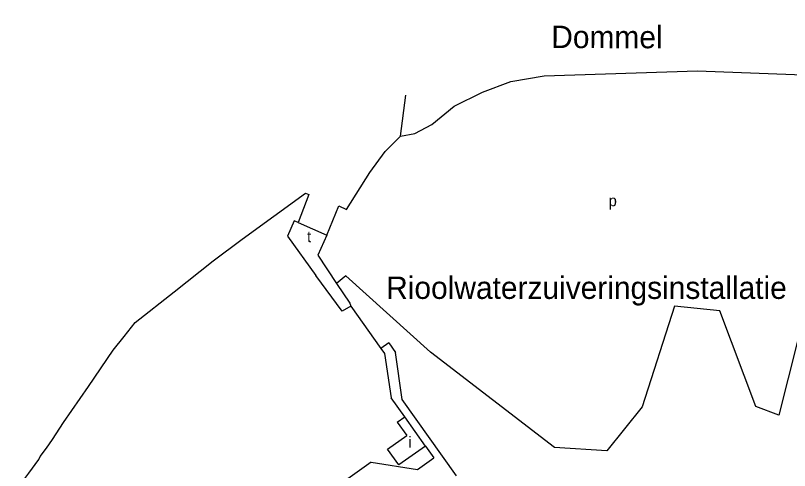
# Model space of a CAD drawing. Extents: x 162427 to 165104, y 384242 to 386287.
# Drawn here: x 162986.7 to 163263.6, y 385814.9 to 385977.6 of the extents above; entities that cross this region are included whole.
import ezdxf

# ---------------------------------------------------------------- set-up
doc = ezdxf.new("R2010")
doc.units = 0
for name, color, linetype in [('BLT_Basislijn', 7, 'Continuous'), ('BLT_Bebouwing', 7, 'Continuous'), ('BLT_Centroide', 7, 'Continuous'), ('BLT_Terrein_beschrifting', 7, 'Continuous'), ('BLT_Vlakafsluiter', 7, 'Continuous'), ('BLT_Waternaam_spoorwegen', 7, 'Continuous')]:
    doc.layers.add(name, color=color, linetype=linetype)

msp = doc.modelspace()

# ---------------------------------------------------------------- linework, layer by layer
at = {"layer": 'BLT_Basislijn'}
for p, q in [((163087.86, 385903.56), (163098.12, 385899.02)), ((163084.03, 385898.67), (163094.14, 385884.68)), ((163098.12, 385899.02), (163094.88, 385891.85)), ((163094.88, 385891.85), (163101.56, 385881.81)), ((163104.9, 385884.54), (163101.56, 385881.81)), ((163135.21, 385857.18), (163104.9, 385884.54)), ((163106.74, 385873.61), (163117.4, 385858.58)), ((163120.24, 385860.59), (163117.4, 385858.58)), ((163120.24, 385860.59), (163122.69, 385857.14)), ((163117.4, 385858.58), (163118.68, 385856.78)), ((163118.68, 385856.78), (163121.09, 385840.94)), ((163125.05, 385840.31), (163122.69, 385857.14)), ((163125.94, 385834.11), (163121.09, 385840.94)), ((163144.44, 385812.98), (163125.05, 385840.31)), ((163133.36, 385823.65), (163136.38, 385819.4)), ((163113.98, 385817.86), (163042.08, 385767.08)), ((163113.98, 385817.86), (163130.49, 385815.22)), ((163130.49, 385815.22), (163136.38, 385819.4))]:
    msp.add_line(p, q, dxfattribs=at)
for points in [[(163124.41, 385934.5), (163129.57, 385935.37), (163135.63, 385938.66), (163143.7, 385945.16), (163153.77, 385950.25), (163163.88, 385954.07), (163175.88, 385956.06), (163230.64, 385957.87), (163290.67, 385955.61), (163310.91, 385957.64), (163330.9, 385965.31), (163350, 385977.63)], [(163098.12, 385899.02), (163102.38, 385909.54), (163105.18, 385908.26), (163113.48, 385921.43), (163118.91, 385928.97), (163124.41, 385934.5)], [(163079.13, 385905.9), (163090.5, 385914.12), (163091.64, 385913.63), (163087.86, 385903.56)], [(163029.49, 385867.77), (163043.44, 385878.84), (163057.39, 385889.9), (163067.77, 385897.68), (163079.13, 385905.9)], [(163087.86, 385903.56), (163086.46, 385904.19), (163084.03, 385898.67)], [(163276.69, 385901.75), (163259.84, 385834.66), (163251.59, 385837.75), (163238.64, 385871.94), (163222.45, 385873.61), (163210.9, 385837.64), (163198.27, 385821.91), (163179.51, 385823.06), (163135.21, 385857.18)], [(163106.74, 385873.61), (163103.55, 385871.86), (163094.14, 385884.68)], [(163101.56, 385881.81), (163106.3, 385874.68), (163106.74, 385873.61)], [(163003.85, 385832.01), (163012.79, 385844.98), (163021.72, 385857.94), (163025.6, 385862.86), (163029.49, 385867.77)], [(162986.73, 385806.97), (162987.92, 385809.21), (162991.49, 385813.99), (162995.07, 385818.77), (162995.6, 385819.85), (162997.8, 385822.92), (163000, 385826), (163003.85, 385832.01)]]:
    msp.add_lwpolyline(points, dxfattribs=at)
at = {"layer": 'BLT_Bebouwing'}
for p, q in [((163123.28, 385832.22), (163125.94, 385834.11)), ((163133.36, 385823.65), (163125.94, 385834.11)), ((163123.28, 385832.22), (163126.71, 385827.38)), ((163119.84, 385822.5), (163126.71, 385827.38)), ((163133.36, 385823.65), (163123.83, 385816.89)), ((163123.83, 385816.89), (163119.84, 385822.5))]:
    msp.add_line(p, q, dxfattribs=at)
at = {"layer": 'BLT_Vlakafsluiter'}
msp.add_line((163124.41, 385934.5), (163126.3, 385949.07), dxfattribs=at)

# ---------------------------------------------------------------- texts
at = {"layer": 'BLT_Centroide'}
for s, p in [('p', (163198.87, 385909.41)), ('t', (163091.02, 385896.53)), ('i', (163127.29, 385823.03))]:
    msp.add_text(s, height=4, dxfattribs=at).set_placement(p)
at = {"layer": 'BLT_Terrein_beschrifting'}
msp.add_text('Rioolwaterzuiveringsinstallatie', height=8, dxfattribs=at).set_placement((163119.33, 385876.26))
at = {"layer": 'BLT_Waternaam_spoorwegen'}
msp.add_text('Dommel', height=8, rotation=359.8515, dxfattribs=at).set_placement((163178.37, 385965.99))

doc.saveas('drawing.dxf')
